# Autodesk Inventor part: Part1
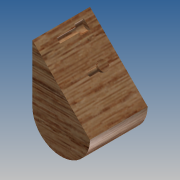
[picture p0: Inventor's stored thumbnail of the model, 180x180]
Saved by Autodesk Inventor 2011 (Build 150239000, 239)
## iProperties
Created: 2011-01
Part Number: Part1
Document SubType Name: Modeling
Designer: Microsoft
Density: 1 g/cm^3
Author: Microsoft
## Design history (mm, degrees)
sketch "Sketch1"
  geometry: L1 (9.525, 0)-(9.525, 19.05); L2 (-9.525, 19.05)-(-9.525, 0); L3 (-9.525, 19.05)-(9.525, 0); A1 r 9.525 centre (0, 0) between (-9.525, 0) and (9.525, 0); A2 r 9.525 centre (0, 19.05) between (9.525, 19.05) and (-9.525, 19.05); 1 further point
  constraints: 6 end point, 4 point on circle, 3 tangent, 2 centre point, 1 coincident, 1 vertical alignment
  dimensions: "d3" = 9.525 radius of A2; "d4" = 9.525 radius of A1; "d5" = 19.05 distance of L1.start L1.end; "d6" = 19.05 distance of point (0, 0) A2.centre
extrude "Extrusion1" new body sketch "Sketch1" distance "d7" = 19.05; taper "d8" = 0 deg
sketch "Sketch2"
  geometry: L1 (13.47, 0)-(13.47, 19.05) reference; C1 r 0.794 at (13.47, 9.525); 1 further point
  constraints: 1 centre point, 1 midpoint
  dimensions: "d9" = 1.5875 diameter of C1
extrude "Extrusion2" join sketch "Sketch2" distance "d10" = 6.35; taper "d11" = 0 deg
sketch "Sketch3"
  geometry: C1 r 0.794 at (0, 0) reference; C2 r 1.587 at (0, 0); 1 further point
  constraints: 1 centre point, 1 coincident
  dimensions: "d12" = 3.175 diameter of C2
extrude "Extrusion3" join sketch "Sketch3" distance "d13" = 0.79375; taper "d14" = 0 deg
workplane "Work Plane1"
sketch "Sketch5"
  geometry: L1 (-9.525, 19.05)-(-8.622, 19.953); L2 (9.525, 0)-(-9.525, 19.05) reference; C1 r 0.794 at (-7.28, 16.805); 1 further point
  constraints: 2 end point, 1 centre point, 1 perpendicular, 1 point on line
  dimensions: "d21" = 1.5875 diameter of C1; "d22" = 3.175 distance from line of L1 C1.centre
extrude "Extrusion4" cut sketch "Sketch5" distance "d23" = 6.35; taper "d24" = 0 deg
sketch "Sketch6"
  geometry: C1 r 1.588 at (-7.28, 16.805); A1 r 0.794 centre (-7.28, 16.805) between (-7.841, 17.366) and (-6.719, 16.244) reference; 1 further point
  constraints: 1 centre point, 1 coincident
  dimensions: "d25" = 3.175 diameter of C1
extrude "Extrusion5" cut sketch "Sketch6" distance "d26" = 3.175; taper "d27" = 0 deg
body "Solid1"
other parameters: "d17" = -6.35
